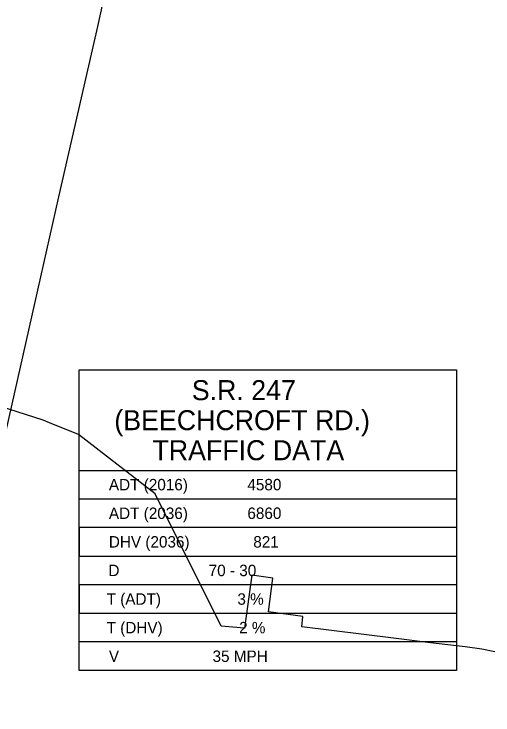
# Model space of a CAD drawing. Extents: x 1577619 to 1828281, y 483481 to 598136.
# Drawn here: x 1695627 to 1704006, y 505510 to 517765 of the extents above; entities that cross this region are included whole.
import ezdxf

# ---------------------------------------------------------------- set-up
doc = ezdxf.new("R2010")
doc.units = 0
for name, color, linetype in [('DESIGN - SHEET - Corner Text', 7, 'Continuous'), ('DESIGN - SHEET - Linework', 7, 'Continuous'), ('SURVEY - CENTERLINE - Preliminary', 7, 'Continuous'), ('SURVEY - DRAINAGE - Natural Features', 7, 'Continuous')]:
    doc.layers.add(name, color=color, linetype=linetype)

msp = doc.modelspace()

# ---------------------------------------------------------------- linework, layer by layer
at = {"layer": 'DESIGN - SHEET - Linework'}
for points in [[(1696769, 509787), (1696769, 511544), (1703369, 511544), (1703369, 506287), (1696769, 506287), (1696769, 509787), (1703369, 509787)], [(1696769, 509287), (1703369, 509287), (1703369, 508787), (1696769, 508787), (1696769, 508287), (1703369, 508287), (1703369, 507787), (1696769, 507787), (1696769, 507287), (1703369, 507287), (1703369, 506787), (1696769, 506787)]]:
    msp.add_lwpolyline(points, dxfattribs=at)
at = {"layer": 'SURVEY - CENTERLINE - Preliminary'}
msp.add_lwpolyline([(1694013, 503946), (1694369, 505553), (1694876, 507798), (1695489, 510480), (1695992, 512706), (1696413, 514571), (1697091, 517545), (1697511, 519468), (1698047, 522105)], dxfattribs=at)
msp.add_lwpolyline([(1694013, 503946), (1694369, 505553), (1694876, 507798), (1695489, 510480), (1695992, 512706), (1696413, 514571), (1697091, 517545), (1697511, 519468), (1698047, 522105)], dxfattribs=at)
at = {"layer": 'SURVEY - DRAINAGE - Natural Features'}
msp.add_lwpolyline([(1704037, 506612), (1703810, 506661), (1703521, 506699), (1702914, 506770), (1702265, 506854), (1702265, 506854), (1700661, 507050), (1700678, 507233), (1700081, 507314), (1700152, 507899), (1699789, 507957), (1699658, 507025), (1699253, 507064), (1698098, 509375), (1696753, 510415), (1696250, 510615), (1696136, 510664), (1691163, 512254)], dxfattribs=at)
msp.add_lwpolyline([(1704037, 506612), (1703810, 506661), (1703521, 506699), (1702914, 506770), (1702265, 506854), (1702265, 506854), (1700661, 507050), (1700678, 507233), (1700081, 507314), (1700152, 507899), (1699789, 507957), (1699658, 507025), (1699253, 507064), (1698098, 509375), (1696753, 510415), (1696250, 510615), (1696136, 510664), (1691163, 512254)], dxfattribs=at)

# ---------------------------------------------------------------- texts
at = {"layer": 'DESIGN - SHEET - Corner Text'}
for s, height, p in [('S.R. 247', 350, (1698737, 511014)), ('(BEECHCROFT RD.)', 350, (1697382, 510489)), ('TRAFFIC DATA', 350, (1698049, 509964)), ('ADT (2016)              4580', 200, (1697287, 509437)), ('ADT (2036)              6860', 200, (1697287, 508937)), ('DHV (2036)               821', 200, (1697286, 508437)), ('D                     70 - 30', 200, (1697279, 507937)), ('T (ADT)                  3 %', 200, (1697247, 507437)), ('T (DHV)                  2 %', 200, (1697247, 506937)), ('V                      35 MPH', 200, (1697287, 506437))]:
    msp.add_text(s, height=height, dxfattribs=at).set_placement(p)

doc.saveas('drawing.dxf')
